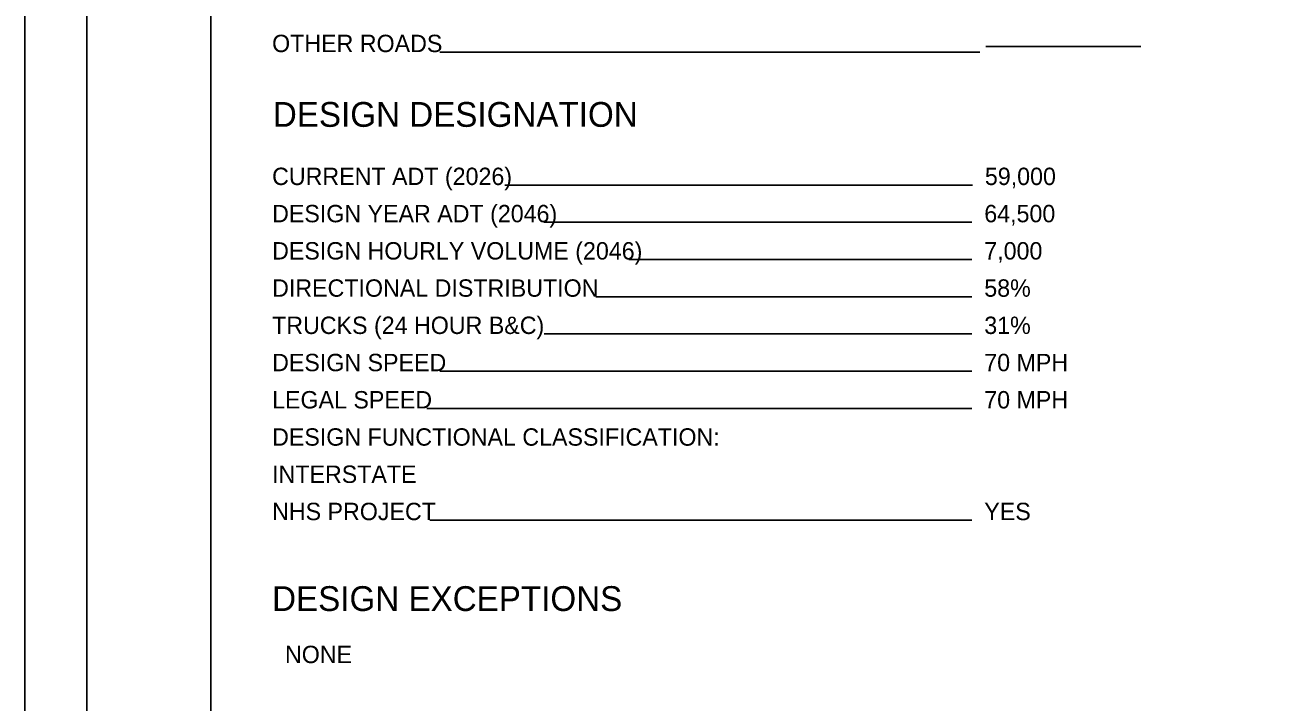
# Model space of a CAD drawing. Extents: x 0 to 34, y 0 to 22.
# Drawn here: x 0 to 10.01, y 5.64 to 11.1 of the extents above; entities that cross this region are included whole.
import ezdxf

# ---------------------------------------------------------------- set-up
doc = ezdxf.new("R2010")
doc.units = 0
for name, color, linetype in [('SH_Border', 7, 'Continuous'), ('SH_Cut_Line', 7, 'Continuous'), ('SH_Data', 7, 'Continuous'), ('SH_Text', 7, 'Continuous')]:
    doc.layers.add(name, color=color, linetype=linetype)

msp = doc.modelspace()

# ---------------------------------------------------------------- linework, layer by layer
at = {"layer": 'SH_Border'}
for points in [[(0.5, 21.5), (1.5, 21.5), (1.5, 0.5), (0.5, 0.5)], [(1.5, 21.5), (33.5, 21.5), (33.5, 0.5), (1.5, 0.5)]]:
    msp.add_lwpolyline(points, close=True, dxfattribs=at)
at = {"layer": 'SH_Cut_Line'}
msp.add_lwpolyline([(0, 0), (34, 0), (34, 22), (0, 22)], close=True, dxfattribs=at)
at = {"layer": 'SH_Data'}
for p, q in [((9, 10.922), (7.75, 10.922)), ((7.7, 10.877), (3.347, 10.877)), ((7.642, 9.806), (3.871, 9.806)), ((7.637, 9.506), (4.189, 9.506)), ((7.637, 9.206), (4.872, 9.206)), ((7.637, 8.906), (4.604, 8.906)), ((7.637, 8.606), (4.189, 8.606)), ((7.637, 8.306), (3.346, 8.306)), ((7.637, 8.006), (3.242, 8.006)), ((7.637, 7.106), (3.267, 7.106))]:
    msp.add_line(p, q, dxfattribs=at)

# ---------------------------------------------------------------- texts
msp.add_text('DESIGN DESIGNATION', height=0.2, dxfattribs=at).set_placement((2, 10.275))
at = {"layer": 'SH_Text'}
for s, height, p in [('OTHER ROADS', 0.14, (1.994, 10.877)), ('CURRENT ADT (2026)', 0.14, (1.994, 9.806)), ('59,000', 0.14, (7.742, 9.806)), ('DESIGN YEAR ADT (2046)', 0.14, (1.994, 9.506)), ('64,500', 0.14, (7.737, 9.506)), ('DESIGN HOURLY VOLUME (2046)', 0.14, (1.994, 9.206)), ('7,000 ', 0.14, (7.737, 9.206)), ('DIRECTIONAL DISTRIBUTION', 0.14, (1.994, 8.906)), ('58%   ', 0.14, (7.737, 8.906)), ('TRUCKS (24 HOUR B&C)', 0.14, (1.994, 8.606)), ('31%   ', 0.14, (7.737, 8.606)), ('DESIGN SPEED', 0.14, (1.994, 8.306)), ('70 MPH', 0.14, (7.737, 8.306)), ('LEGAL SPEED', 0.14, (1.994, 8.006)), ('70 MPH', 0.14, (7.737, 8.006)), ('DESIGN FUNCTIONAL CLASSIFICATION:', 0.14, (1.994, 7.706)), ('INTERSTATE', 0.14, (1.994, 7.406)), ('NHS PROJECT', 0.14, (1.994, 7.106)), ('YES', 0.14, (7.737, 7.106)), ('DESIGN EXCEPTIONS', 0.2, (1.994, 6.374)), ('  NONE                                   ', 0.14, (1.994, 5.954))]:
    msp.add_text(s, height=height, dxfattribs=at).set_placement(p)

doc.saveas('drawing.dxf')
